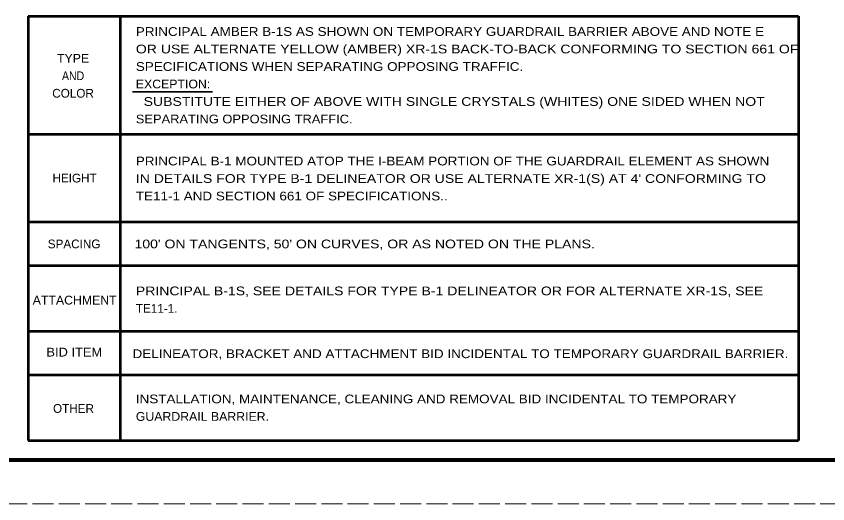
# Model space of a CAD drawing. Extents: x -60 to 620, y -42 to 398.
# Drawn here: x 155.3 to 340.7, y -41.8 to 69.7 of the extents above; entities that cross this region are included whole.
import ezdxf
from ezdxf.enums import TextEntityAlignment as Align

# ---------------------------------------------------------------- set-up
doc = ezdxf.new("R2010")
doc.units = 0
doc.header["$LTSCALE"] = 0.8
doc.linetypes.add('LONG_DASHED', pattern=[7.5, 6, -1.5])
doc.layers.add('1', color=7, linetype='Continuous', lineweight=35)
doc.layers.add('61', color=7, linetype='Continuous', lineweight=35)

msp = doc.modelspace()

# ---------------------------------------------------------------- linework, layer by layer
at = {"layer": '1', "lineweight": 53}
for p, q in [((158.0131, 69.7191), (334.0131, 69.7191)), ((158.0131, 69.7191), (158.0131, -27.2809)), ((179.0131, 69.7191), (179.0131, -27.2809)), ((334.0131, 69.7191), (334.0131, -27.2809)), ((158.0131, 42.7191), (334.0131, 42.7191)), ((158.0131, 22.7191), (334.0131, 22.7191)), ((158.0131, 12.7191), (334.0131, 12.7191)), ((158.0131, -2.2809), (334.0131, -2.2809)), ((158.0131, -12.2809), (334.0131, -12.2809)), ((158.0131, -27.2809), (334.0131, -27.2809))]:
    msp.add_line(p, q, dxfattribs=at)
at = {"layer": '1'}
msp.add_line((181.8031, 52.4213), (200.103, 52.4213), dxfattribs=at)
at = {"layer": '61', "lineweight": 158}
msp.add_line((608.8445, -31.7712), (-30.2155, -31.7512), dxfattribs=at)
at = {"layer": '61', "linetype": 'LONG_DASHED', "lineweight": 13}
msp.add_line((619.7845, -41.7512), (-60.2755, -41.7713), dxfattribs=at)

# ---------------------------------------------------------------- texts
at = {"layer": '1'}
for s, width, p in [('PRINCIPAL AMBER B-1S AS SHOWN ON TEMPORARY GUARDRAIL BARRIER ABOVE AND NOTE E', 1.15, (182.5905, 65.2158)), ('OR USE ALTERNATE YELLOW (AMBER) XR-1S BACK-TO-BACK CONFORMING TO SECTION 661 OF', 1.2, (182.5905, 61.2158)), ('SPECIFICATIONS WHEN SEPARATING OPPOSING TRAFFIC.', 1.15, (182.5905, 57.2158)), ('EXCEPTION:', 1.05, (182.5905, 53.2158)), ('  SUBSTITUTE EITHER OF ABOVE WITH SINGLE CRYSTALS (WHITES) ONE SIDED WHEN NOT', 1.2, (182.5905, 49.2158)), ('SEPARATING OPPOSING TRAFFIC.', 1.1, (182.5905, 45.2158)), ('PRINCIPAL B-1 MOUNTED ATOP THE I-BEAM PORTION OF THE GUARDRAIL ELEMENT AS SHOWN', 1.15, (182.5905, 35.6007)), ("IN DETAILS FOR TYPE B-1 DELINEATOR OR USE ALTERNATE XR-1(S) AT 4' CONFORMING TO", 1.2, (182.5905, 31.6007)), ('TE11-1 AND SECTION 661 OF SPECIFICATIONS..', 1.15, (182.5905, 27.6007)), ('PRINCIPAL B-1S, SEE DETAILS FOR TYPE B-1 DELINEATOR OR FOR ALTERNATE XR-1S, SEE', 1.2, (182.5905, 5.9037)), ('INSTALLATION, MAINTENANCE, CLEANING AND REMOVAL BID INCIDENTAL TO TEMPORARY', 1.15, (182.5905, -18.8008)), ('GUARDRAIL BARRIER.', 1.05, (182.5905, -22.8008))]:
    msp.add_text(s, height=2, dxfattribs=dict(at, width=width)).set_placement(p)
for s, width, p in [('TYPE', 1.05, (168.2501, 59.1009)), ('AND', 0.9, (168.2501, 55.1009)), ("100' ON TANGENTS, 50' ON CURVES, OR AS NOTED ON THE PLANS.", 1.2, (234.8827, 16.6428)), ('ATTACHMENT', 1.05, (168.6203, 3.7973)), ('BID ITEM', 1.1, (168.534, -8.0928)), ('DELINEATOR, BRACKET AND ATTACHMENT BID INCIDENTAL TO TEMPORARY GUARDRAIL BARRIER.', 1.15, (256.765, -8.4656))]:
    msp.add_text(s, height=2, dxfattribs=dict(at, width=width)).set_placement(p, align=Align.CENTER)
for s, p in [('COLOR', (168.25, 51.1009)), ('HEIGHT', (168.5908, 31.7097)), ('SPACING', (168.4878, 16.6468)), ('OTHER', (168.349, -20.9772))]:
    msp.add_text(s, height=2, dxfattribs=at).set_placement(p, align=Align.CENTER)
msp.add_text('TE11-1.', height=2, dxfattribs=at).set_placement((182.5905, 1.9037))

doc.saveas('drawing.dxf')
